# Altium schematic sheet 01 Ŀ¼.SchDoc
size 297 x 209 mm
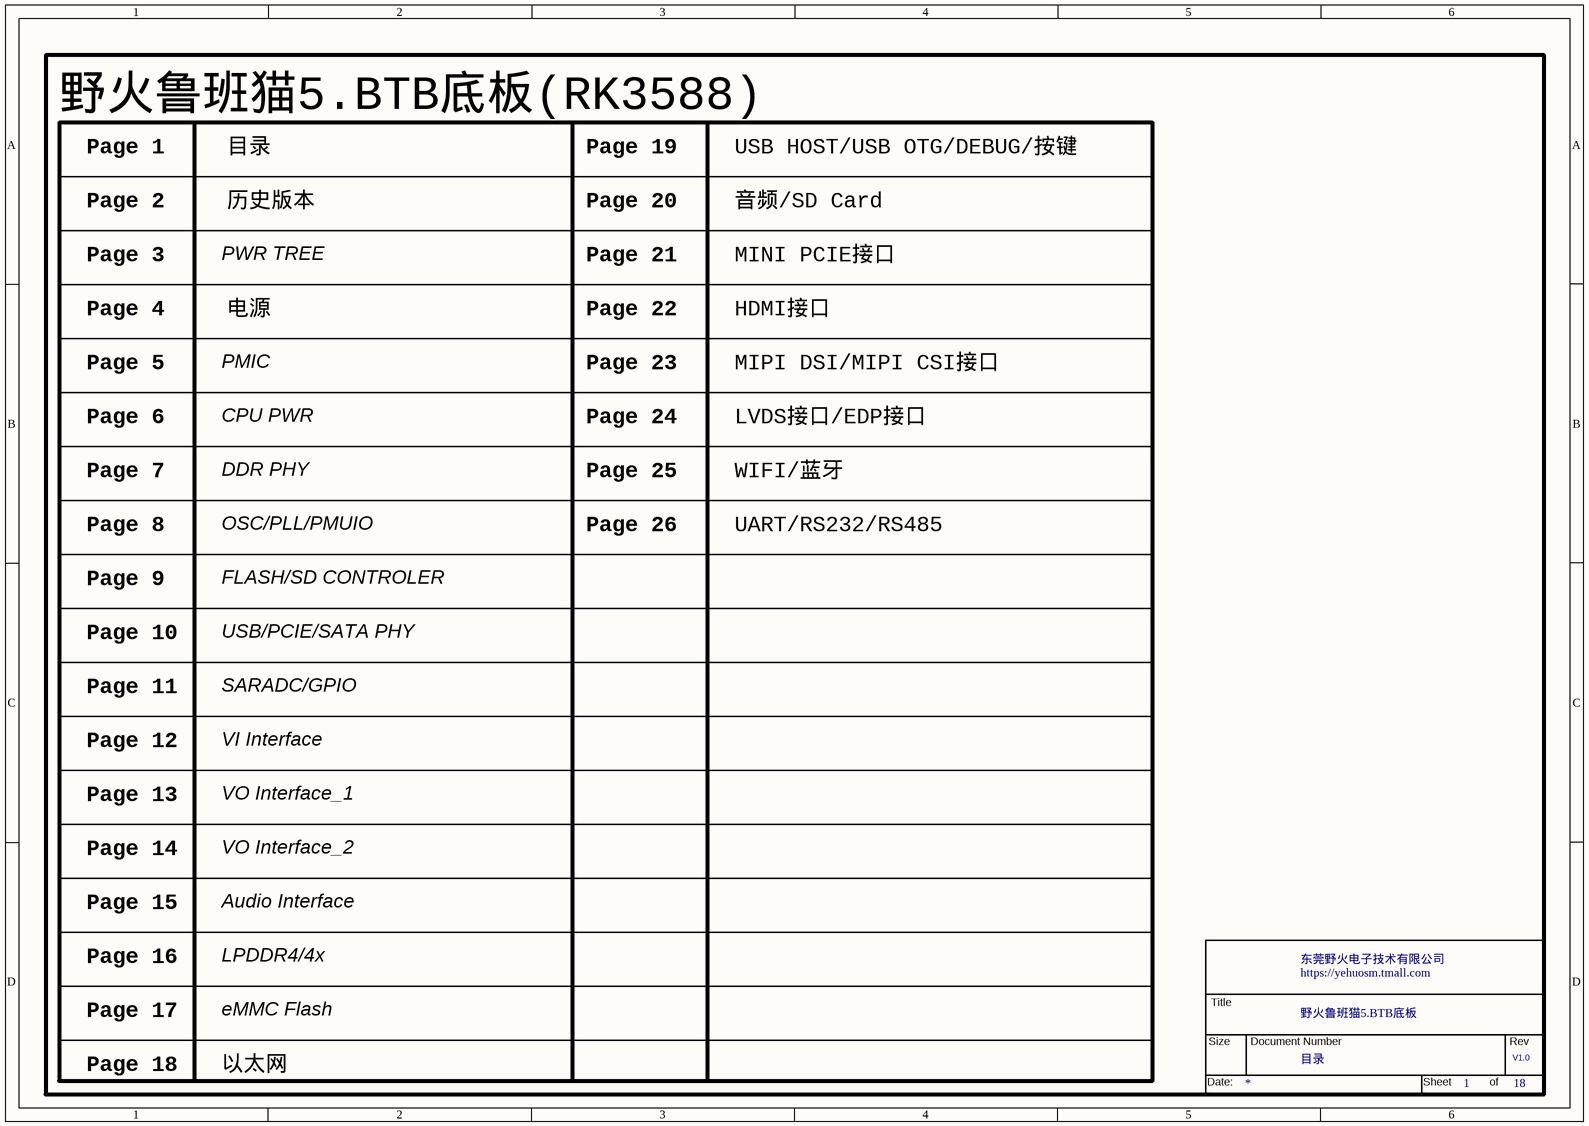
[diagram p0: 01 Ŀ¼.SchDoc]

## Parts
*  Doc: 目录  RevCode: V1.0  Title: 野火鲁班猫5.BTB底板  OrgName: 东莞野火电子技术有限公司  Page Number: 1  Page Count: 18  (hidden comment: TitleBlock_YHSCH)  (graphical)

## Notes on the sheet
- 野火鲁班猫5.BTB底板(RK3588)
- Page 1
- 目录
- Page 19
- USB HOST/USB OTG/DEBUG/按键
- Page 2
- Page 3
- PWR TREE
- 历史版本
- Page 20
- Page 21
- 音频/SD Card
- MINI PCIE接口
- Page 4
- 电源
- Page 22
- HDMI接口
- Page 5
- PMIC
- Page 23
- MIPI DSI/MIPI CSI接口
- Page 6
- CPU PWR
- Page 24
- LVDS接口/EDP接口
- Page 8
- Page 7
- OSC/PLL/PMUIO
- DDR PHY
- Page 25
- Page 26
- WIFI/蓝牙
- UART/RS232/RS485
- Page 9
- FLASH/SD CONTROLER
- Page 10
- USB/PCIE/SATA PHY
- Page 11
- SARADC/GPIO
- Page 12
- Page 13
- VI Interface
- VO Interface_1
- Page 14
- VO Interface_2
- Page 15
- Audio Interface
- Page 16
- LPDDR4/4x
- Page 17
- Page 18
- eMMC Flash
- 以太网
